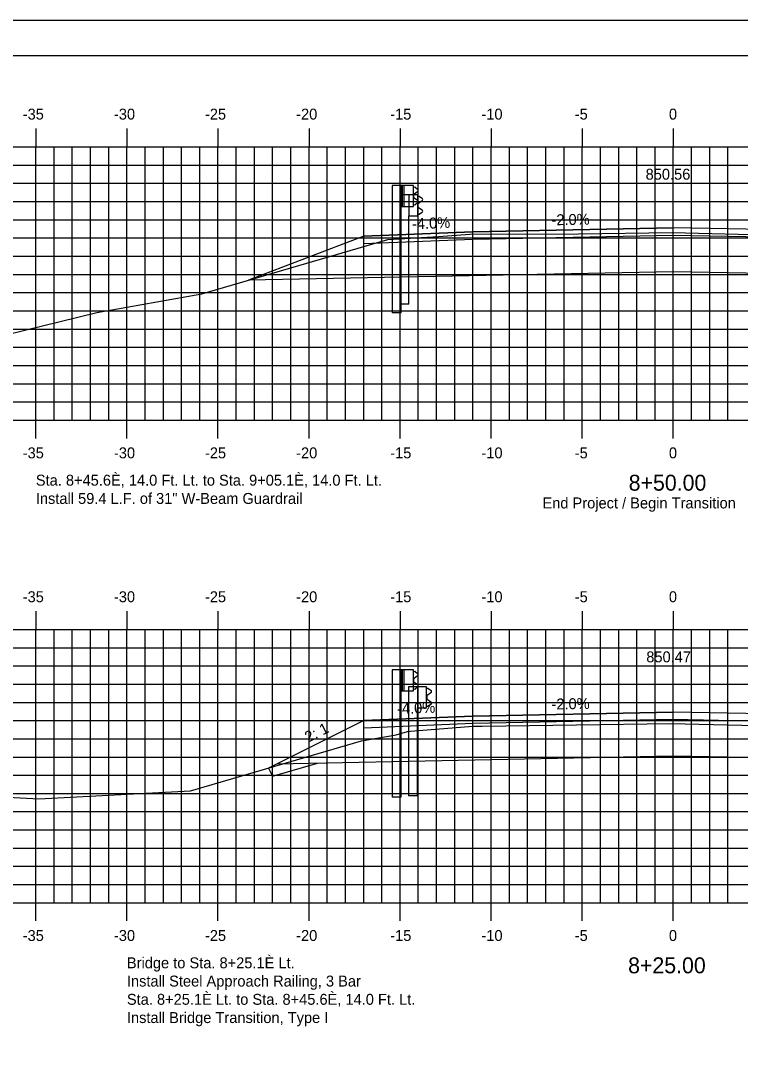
# Model space of a CAD drawing. Extents: x 2194256 to 2194747, y 863888 to 863998.
# Drawn here: x 2194440.9 to 2194480.4, y 863942.1 to 863998.4 of the extents above; entities that cross this region are included whole.
import ezdxf

# ---------------------------------------------------------------- set-up
doc = ezdxf.new("R2010")
doc.units = 0
for name, color, linetype in [('ANNOTATION', 7, 'Continuous'), ('BORDER', 7, 'Continuous'), ('D_Guardrail_Beam_Lt', 7, 'Continuous'), ('H_V ANNOTATION', 7, 'Continuous'), ('MAJOR', 7, 'Continuous'), ('MINOR', 7, 'Continuous'), ('PLOT BOUNDARY', 7, 'Continuous'), ('S_Guardrail_Beam', 7, 'Continuous'), ('S_Roadway_Centerline', 7, 'Continuous'), ('TEMPLATE', 7, 'Continuous')]:
    doc.layers.add(name, color=color, linetype=linetype)

msp = doc.modelspace()

# ---------------------------------------------------------------- linework, layer by layer
at = {"layer": 'BORDER'}
msp.add_lwpolyline([(2194401.743, 863891.446), (2194561.743, 863891.446), (2194561.743, 863996.446), (2194401.743, 863996.446)], close=True, dxfattribs=at)
at = {"layer": 'D_Guardrail_Beam_Lt'}
for p, q in [((2194461.314, 863989.332), (2194461.314, 863982.332)), ((2194461.784, 863989.332), (2194461.314, 863989.332)), ((2194462.472, 863989.332), (2194461.784, 863989.332)), ((2194461.784, 863989.332), (2194461.784, 863988.166)), ((2194461.847, 863989.332), (2194461.847, 863988.166)), ((2194461.951, 863989.332), (2194461.951, 863988.166)), ((2194462.472, 863988.166), (2194462.472, 863989.332)), ((2194462.472, 863989.249), (2194462.546, 863989.235)), ((2194462.705, 863988.985), (2194462.51, 863988.849)), ((2194462.562, 863989.228), (2194462.705, 863989.128)), ((2194462.476, 863988.784), (2194462.476, 863988.714)), ((2194462.51, 863988.65), (2194462.705, 863988.513)), ((2194462.705, 863988.37), (2194462.562, 863988.27)), ((2194461.784, 863988.166), (2194462.472, 863988.166)), ((2194461.805, 863982.332), (2194461.805, 863988.166)), ((2194462.546, 863988.264), (2194462.472, 863988.249)), ((2194461.805, 863982.332), (2194461.314, 863982.332)), ((2194461.314, 863962.742), (2194461.314, 863955.742)), ((2194461.784, 863962.742), (2194461.314, 863962.742)), ((2194462.472, 863962.742), (2194461.784, 863962.742)), ((2194461.784, 863962.742), (2194461.784, 863961.576)), ((2194461.847, 863962.742), (2194461.847, 863961.576)), ((2194461.951, 863962.742), (2194461.951, 863961.576)), ((2194462.472, 863961.576), (2194462.472, 863962.742)), ((2194462.472, 863962.659), (2194462.546, 863962.645)), ((2194462.562, 863962.638), (2194462.705, 863962.538)), ((2194462.476, 863962.194), (2194462.476, 863962.124)), ((2194462.705, 863962.395), (2194462.51, 863962.259)), ((2194462.51, 863962.06), (2194462.705, 863961.923)), ((2194461.784, 863961.576), (2194462.472, 863961.576)), ((2194461.805, 863955.742), (2194461.805, 863961.576)), ((2194462.546, 863961.674), (2194462.472, 863961.659)), ((2194462.705, 863961.78), (2194462.562, 863961.68)), ((2194461.805, 863955.742), (2194461.314, 863955.742))]:
    msp.add_line(p, q, dxfattribs=at)
for centre, major_axis, start_param, end_param in [((2194462.538, 863989.194), (0.0417, 0), 0.959931, 1.376053), ((2194462.655, 863989.056), (0.0877, 0), 5.323254, 7.243116), ((2194462.555, 863988.784), (-0.0789, 0), 5.323254, 6.283185), ((2194462.555, 863988.714), (-0.0789, 0), 6.283185, 7.243116), ((2194462.655, 863988.442), (0.0877, 0), 5.323254, 7.243116), ((2194462.538, 863988.304), (0.0417, 0), 4.907132, 5.323254), ((2194462.538, 863962.604), (0.0417, 0), 0.959931, 1.376053), ((2194462.655, 863962.466), (0.0877, 0), 5.323254, 7.243116), ((2194462.555, 863962.194), (-0.0789, 0), 5.323254, 6.283185), ((2194462.555, 863962.124), (-0.0789, 0), 6.283185, 7.243116), ((2194462.655, 863961.852), (0.0877, 0), 5.323254, 7.243116), ((2194462.538, 863961.714), (0.0417, 0), 4.907132, 5.323254)]:
    msp.add_ellipse(centre, major_axis=major_axis, ratio=0.995501, start_param=start_param, end_param=end_param, dxfattribs=at)
at = {"layer": 'MAJOR'}
for p, q in [((2194441.743, 863992.448), (2194441.743, 863991.446)), ((2194446.743, 863992.448), (2194446.743, 863991.446)), ((2194451.743, 863992.448), (2194451.743, 863991.446)), ((2194456.743, 863992.448), (2194456.743, 863991.446)), ((2194461.743, 863992.448), (2194461.743, 863991.446)), ((2194466.743, 863992.448), (2194466.743, 863991.446)), ((2194471.743, 863992.448), (2194471.743, 863991.446)), ((2194476.743, 863992.448), (2194476.743, 863991.446)), ((2194406.743, 863991.446), (2194546.743, 863991.446)), ((2194441.743, 863976.446), (2194441.743, 863991.446)), ((2194446.743, 863976.446), (2194446.743, 863991.446)), ((2194451.743, 863976.446), (2194451.743, 863991.446)), ((2194456.743, 863976.446), (2194456.743, 863991.446)), ((2194461.743, 863976.446), (2194461.743, 863991.446)), ((2194466.743, 863976.446), (2194466.743, 863991.446)), ((2194471.743, 863976.446), (2194471.743, 863991.446)), ((2194476.743, 863976.446), (2194476.743, 863991.446)), ((2194406.743, 863986.446), (2194546.743, 863986.446)), ((2194406.743, 863981.446), (2194546.743, 863981.446)), ((2194406.743, 863976.446), (2194546.743, 863976.446)), ((2194441.743, 863975.444), (2194441.743, 863976.446)), ((2194446.743, 863975.444), (2194446.743, 863976.446)), ((2194451.743, 863975.444), (2194451.743, 863976.446)), ((2194456.743, 863975.444), (2194456.743, 863976.446)), ((2194461.743, 863975.444), (2194461.743, 863976.446)), ((2194466.743, 863975.444), (2194466.743, 863976.446)), ((2194471.743, 863975.444), (2194471.743, 863976.446)), ((2194476.743, 863975.444), (2194476.743, 863976.446)), ((2194441.743, 863965.948), (2194441.743, 863964.946)), ((2194446.743, 863965.948), (2194446.743, 863964.946)), ((2194451.743, 863965.948), (2194451.743, 863964.946)), ((2194456.743, 863965.948), (2194456.743, 863964.946)), ((2194461.743, 863965.948), (2194461.743, 863964.946)), ((2194466.743, 863965.948), (2194466.743, 863964.946)), ((2194471.743, 863965.948), (2194471.743, 863964.946)), ((2194476.743, 863965.948), (2194476.743, 863964.946)), ((2194406.743, 863964.946), (2194546.743, 863964.946)), ((2194406.743, 863964.946), (2194546.743, 863964.946)), ((2194441.743, 863949.946), (2194441.743, 863964.946)), ((2194446.743, 863949.946), (2194446.743, 863964.946)), ((2194451.743, 863949.946), (2194451.743, 863964.946)), ((2194456.743, 863949.946), (2194456.743, 863964.946)), ((2194461.743, 863949.946), (2194461.743, 863964.946)), ((2194466.743, 863949.946), (2194466.743, 863964.946)), ((2194471.743, 863949.946), (2194471.743, 863964.946)), ((2194476.743, 863949.946), (2194476.743, 863964.946)), ((2194406.743, 863959.946), (2194546.743, 863959.946)), ((2194406.743, 863954.946), (2194546.743, 863954.946)), ((2194406.743, 863949.946), (2194546.743, 863949.946)), ((2194441.743, 863948.944), (2194441.743, 863949.946)), ((2194446.743, 863948.944), (2194446.743, 863949.946)), ((2194451.743, 863948.944), (2194451.743, 863949.946)), ((2194456.743, 863948.944), (2194456.743, 863949.946)), ((2194461.743, 863948.944), (2194461.743, 863949.946)), ((2194466.743, 863948.944), (2194466.743, 863949.946)), ((2194471.743, 863948.944), (2194471.743, 863949.946)), ((2194476.743, 863948.944), (2194476.743, 863949.946))]:
    msp.add_line(p, q, dxfattribs=at)
at = {"layer": 'MINOR'}
for p, q in [((2194442.743, 863976.446), (2194442.743, 863991.446)), ((2194443.743, 863976.446), (2194443.743, 863991.446)), ((2194444.743, 863976.446), (2194444.743, 863991.446)), ((2194445.743, 863976.446), (2194445.743, 863991.446)), ((2194447.743, 863976.446), (2194447.743, 863991.446)), ((2194448.743, 863976.446), (2194448.743, 863991.446)), ((2194449.743, 863976.446), (2194449.743, 863991.446)), ((2194450.743, 863976.446), (2194450.743, 863991.446)), ((2194452.743, 863976.446), (2194452.743, 863991.446)), ((2194453.743, 863976.446), (2194453.743, 863991.446)), ((2194454.743, 863976.446), (2194454.743, 863991.446)), ((2194455.743, 863976.446), (2194455.743, 863991.446)), ((2194457.743, 863976.446), (2194457.743, 863991.446)), ((2194458.743, 863976.446), (2194458.743, 863991.446)), ((2194459.743, 863976.446), (2194459.743, 863991.446)), ((2194460.743, 863976.446), (2194460.743, 863991.446)), ((2194462.743, 863976.446), (2194462.743, 863991.446)), ((2194463.743, 863976.446), (2194463.743, 863991.446)), ((2194464.743, 863976.446), (2194464.743, 863991.446)), ((2194465.743, 863976.446), (2194465.743, 863991.446)), ((2194467.743, 863976.446), (2194467.743, 863991.446)), ((2194468.743, 863976.446), (2194468.743, 863991.446)), ((2194469.743, 863976.446), (2194469.743, 863991.446)), ((2194470.743, 863976.446), (2194470.743, 863991.446)), ((2194472.743, 863976.446), (2194472.743, 863991.446)), ((2194473.743, 863976.446), (2194473.743, 863991.446)), ((2194474.743, 863976.446), (2194474.743, 863991.446)), ((2194475.743, 863976.446), (2194475.743, 863991.446)), ((2194477.743, 863976.446), (2194477.743, 863991.446)), ((2194478.743, 863976.446), (2194478.743, 863991.446)), ((2194479.743, 863976.446), (2194479.743, 863991.446)), ((2194406.743, 863990.446), (2194546.743, 863990.446)), ((2194406.743, 863989.446), (2194546.743, 863989.446)), ((2194406.743, 863988.446), (2194546.743, 863988.446)), ((2194406.743, 863987.446), (2194546.743, 863987.446)), ((2194406.743, 863985.446), (2194546.743, 863985.446)), ((2194406.743, 863984.446), (2194546.743, 863984.446)), ((2194406.743, 863983.446), (2194546.743, 863983.446)), ((2194406.743, 863982.446), (2194546.743, 863982.446)), ((2194406.743, 863980.446), (2194546.743, 863980.446)), ((2194406.743, 863979.446), (2194546.743, 863979.446)), ((2194406.743, 863978.446), (2194546.743, 863978.446)), ((2194406.743, 863977.446), (2194546.743, 863977.446)), ((2194442.743, 863949.946), (2194442.743, 863964.946)), ((2194443.743, 863949.946), (2194443.743, 863964.946)), ((2194444.743, 863949.946), (2194444.743, 863964.946)), ((2194445.743, 863949.946), (2194445.743, 863964.946)), ((2194447.743, 863949.946), (2194447.743, 863964.946)), ((2194448.743, 863949.946), (2194448.743, 863964.946)), ((2194449.743, 863949.946), (2194449.743, 863964.946)), ((2194450.743, 863949.946), (2194450.743, 863964.946)), ((2194452.743, 863949.946), (2194452.743, 863964.946)), ((2194453.743, 863949.946), (2194453.743, 863964.946)), ((2194454.743, 863949.946), (2194454.743, 863964.946)), ((2194455.743, 863949.946), (2194455.743, 863964.946)), ((2194457.743, 863949.946), (2194457.743, 863964.946)), ((2194458.743, 863949.946), (2194458.743, 863964.946)), ((2194459.743, 863949.946), (2194459.743, 863964.946)), ((2194460.743, 863949.946), (2194460.743, 863964.946)), ((2194462.743, 863949.946), (2194462.743, 863964.946)), ((2194463.743, 863949.946), (2194463.743, 863964.946)), ((2194464.743, 863949.946), (2194464.743, 863964.946)), ((2194465.743, 863949.946), (2194465.743, 863964.946)), ((2194467.743, 863949.946), (2194467.743, 863964.946)), ((2194468.743, 863949.946), (2194468.743, 863964.946)), ((2194469.743, 863949.946), (2194469.743, 863964.946)), ((2194470.743, 863949.946), (2194470.743, 863964.946)), ((2194472.743, 863949.946), (2194472.743, 863964.946)), ((2194473.743, 863949.946), (2194473.743, 863964.946)), ((2194474.743, 863949.946), (2194474.743, 863964.946)), ((2194475.743, 863949.946), (2194475.743, 863964.946)), ((2194477.743, 863949.946), (2194477.743, 863964.946)), ((2194478.743, 863949.946), (2194478.743, 863964.946)), ((2194479.743, 863949.946), (2194479.743, 863964.946)), ((2194406.743, 863963.946), (2194546.743, 863963.946)), ((2194406.743, 863962.946), (2194546.743, 863962.946)), ((2194406.743, 863961.946), (2194546.743, 863961.946)), ((2194406.743, 863960.946), (2194546.743, 863960.946)), ((2194406.743, 863958.946), (2194546.743, 863958.946)), ((2194406.743, 863957.946), (2194546.743, 863957.946)), ((2194406.743, 863956.946), (2194546.743, 863956.946)), ((2194406.743, 863955.946), (2194546.743, 863955.946)), ((2194406.743, 863953.946), (2194546.743, 863953.946)), ((2194406.743, 863952.946), (2194546.743, 863952.946)), ((2194406.743, 863951.946), (2194546.743, 863951.946)), ((2194406.743, 863950.946), (2194546.743, 863950.946))]:
    msp.add_line(p, q, dxfattribs=at)
at = {"layer": 'PLOT BOUNDARY'}
msp.add_lwpolyline([(2194393.65, 863888.387), (2194563.65, 863888.387), (2194563.65, 863998.387), (2194393.65, 863998.387)], close=True, dxfattribs=at)
at = {"layer": 'S_Guardrail_Beam'}
for p, q in [((2194461.726, 863988.82), (2194461.726, 863982.82)), ((2194462.217, 863988.82), (2194461.726, 863988.82)), ((2194462.707, 863988.82), (2194462.217, 863988.82)), ((2194462.217, 863988.82), (2194462.217, 863987.654)), ((2194462.707, 863987.654), (2194462.707, 863988.82)), ((2194462.707, 863988.747), (2194462.789, 863988.733)), ((2194462.949, 863988.483), (2194462.754, 863988.347)), ((2194462.806, 863988.726), (2194462.949, 863988.626)), ((2194462.72, 863988.282), (2194462.72, 863988.191)), ((2194462.754, 863988.127), (2194462.949, 863987.991)), ((2194462.949, 863987.848), (2194462.806, 863987.748)), ((2194462.217, 863982.82), (2194462.217, 863987.654)), ((2194462.217, 863987.654), (2194462.707, 863987.654)), ((2194462.789, 863987.741), (2194462.707, 863987.726)), ((2194462.217, 863982.82), (2194461.726, 863982.82)), ((2194462.209, 863961.807), (2194462.209, 863955.807)), ((2194462.7, 863961.807), (2194462.209, 863961.807)), ((2194463.19, 863961.807), (2194462.7, 863961.807)), ((2194462.7, 863961.807), (2194462.7, 863960.64)), ((2194463.19, 863960.64), (2194463.19, 863961.807)), ((2194463.19, 863961.734), (2194463.272, 863961.719)), ((2194463.432, 863961.47), (2194463.237, 863961.333)), ((2194463.289, 863961.713), (2194463.432, 863961.613)), ((2194463.203, 863961.269), (2194463.203, 863961.178)), ((2194463.237, 863961.114), (2194463.432, 863960.977)), ((2194463.432, 863960.834), (2194463.289, 863960.734)), ((2194462.7, 863955.807), (2194462.7, 863960.64)), ((2194462.7, 863960.64), (2194463.19, 863960.64)), ((2194463.272, 863960.727), (2194463.19, 863960.713)), ((2194462.7, 863955.807), (2194462.209, 863955.807))]:
    msp.add_line(p, q, dxfattribs=at)
for centre, major_axis, start_param, end_param in [((2194462.799, 863988.282), (-0.0789, 0), 5.323254, 6.283185), ((2194462.782, 863988.692), (0.0417, 0), 0.959931, 1.396263), ((2194462.899, 863988.555), (0.0877, 0), 5.323254, 7.243116), ((2194462.799, 863988.191), (-0.0789, 0), 6.283185, 7.243116), ((2194462.899, 863987.919), (0.0877, 0), 5.323254, 7.243116), ((2194462.782, 863987.782), (0.0417, 0), 4.886922, 5.323254), ((2194463.282, 863961.269), (-0.0789, 0), 5.323254, 6.283185), ((2194463.265, 863961.679), (0.0417, 0), 0.959931, 1.396263), ((2194463.382, 863961.541), (0.0877, 0), 5.323254, 7.243116), ((2194463.282, 863961.178), (-0.0789, 0), 6.283185, 7.243116), ((2194463.382, 863960.906), (0.0877, 0), 5.323254, 7.243116), ((2194463.265, 863960.768), (0.0417, 0), 4.886922, 5.323254)]:
    msp.add_ellipse(centre, major_axis=major_axis, ratio=0.995501, start_param=start_param, end_param=end_param, dxfattribs=at)
at = {"layer": 'S_Roadway_Centerline'}
for points in [[(2194406.743, 863984.776), (2194413.814, 863984.462), (2194422.331, 863983.975), (2194424.939, 863983.173), (2194440.092, 863981.136), (2194445.1, 863982.351), (2194450.863, 863983.373), (2194461.063, 863986.367), (2194463.856, 863986.522), (2194465.566, 863986.66), (2194471.54, 863986.672), (2194476.678, 863986.745), (2194482.483, 863986.609), (2194488.569, 863986.453), (2194490.962, 863986.285), (2194492.004, 863986.208), (2194497.241, 863986.134), (2194498.885, 863986.051), (2194505.695, 863985.992)], [(2194436.828, 863955.919), (2194441.916, 863955.643), (2194450.241, 863956.094), (2194459.622, 863958.832), (2194461.531, 863959.171), (2194462.152, 863959.353), (2194462.322, 863959.362), (2194465.731, 863959.637), (2194466.254, 863959.638), (2194476.612, 863959.784), (2194488.315, 863959.51), (2194488.716, 863959.5), (2194489.419, 863959.45), (2194492.028, 863959.243), (2194494.216, 863959.118), (2194496.931, 863958.932), (2194497.146, 863958.884), (2194498.014, 863958.878), (2194503.173, 863959.04), (2194509.394, 863958.986)]]:
    msp.add_lwpolyline(points, dxfattribs=at)
at = {"layer": 'TEMPLATE'}
for p, q in [((2194465.743, 863986.786), (2194459.743, 863986.546)), ((2194465.743, 863986.786), (2194476.743, 863987.006)), ((2194476.743, 863987.006), (2194465.743, 863986.786)), ((2194487.743, 863986.786), (2194476.743, 863987.006)), ((2194459.743, 863986.546), (2194453.417, 863984.123)), ((2194476.743, 863986.589), (2194465.743, 863986.369)), ((2194487.743, 863986.369), (2194476.743, 863986.589)), ((2194476.743, 863984.589), (2194453.417, 863984.123)), ((2194498.527, 863984.153), (2194476.743, 863984.589)), ((2194465.743, 863960.196), (2194459.743, 863959.956)), ((2194465.743, 863960.196), (2194476.743, 863960.416)), ((2194476.743, 863960.416), (2194465.743, 863960.196)), ((2194487.743, 863960.196), (2194476.743, 863960.416)), ((2194459.743, 863959.956), (2194454.513, 863957.341)), ((2194476.743, 863959.999), (2194465.743, 863959.779)), ((2194487.743, 863959.779), (2194476.743, 863959.999)), ((2194476.743, 863957.999), (2194454.958, 863957.563)), ((2194498.527, 863957.563), (2194476.743, 863957.999)), ((2194454.513, 863957.341), (2194454.736, 863956.894))]:
    msp.add_line(p, q, dxfattribs=at)
for points in [[(2194459.743, 863986.546), (2194459.743, 863986.546), (2194465.743, 863986.786)], [(2194465.743, 863986.369), (2194459.743, 863986.129), (2194459.743, 863986.546)], [(2194459.743, 863959.956), (2194459.743, 863959.956), (2194465.743, 863960.196)], [(2194465.743, 863959.779), (2194459.743, 863959.539), (2194459.743, 863959.956)], [(2194454.74, 863956.886), (2194457.214, 863957.609)]]:
    msp.add_lwpolyline(points, dxfattribs=at)

# ---------------------------------------------------------------- texts
at = {"layer": 'ANNOTATION'}
for s, p in [('850.56', (2194475.223, 863989.646)), ('Sta. 8+45.6È, 14.0 Ft. Lt. to Sta. 9+05.1È, 14.0 Ft. Lt.', (2194441.743, 863972.846)), ('Install 59.4 L.F. of 31" W-Beam Guardrail', (2194441.743, 863971.844)), ('End Project / Begin Transition', (2194469.559, 863971.596)), ('850.47', (2194475.26, 863963.146)), ('Bridge to Sta. 8+25.1È Lt.', (2194446.743, 863946.346)), ('Install Steel Approach Railing, 3 Bar', (2194446.743, 863945.344)), ('Sta. 8+25.1È Lt. to Sta. 8+45.6È, 14.0 Ft. Lt.', (2194446.743, 863944.342)), ('Install Bridge Transition, Type I', (2194446.743, 863943.34))]:
    msp.add_text(s, height=0.6, dxfattribs=at).set_placement(p)
for s, rotation, p in [('-2.0%', 1.1458, (2194470.06, 863987.139)), ('-4.0%', 2.2906, (2194462.406, 863986.919)), ('-4.0%', 2.2906, (2194461.588, 863960.297)), ('-2.0%', 1.1458, (2194470.06, 863960.549)), ('2: 1', 26.5651, (2194456.692, 863958.729))]:
    msp.add_text(s, height=0.6, rotation=rotation, dxfattribs=at).set_placement(p)
at = {"layer": 'H_V ANNOTATION'}
for s, height, p in [('-35', 0.6, (2194441.023, 863992.946)), ('-30', 0.6, (2194446.031, 863992.946)), ('-25', 0.6, (2194451.028, 863992.946)), ('-20', 0.6, (2194456.036, 863992.946)), ('-15', 0.6, (2194461.2, 863992.946)), ('-10', 0.6, (2194466.208, 863992.946)), ('-5', 0.6, (2194471.333, 863992.946)), ('0', 0.6, (2194476.502, 863992.946)), ('-35', 0.6, (2194441.023, 863974.346)), ('-30', 0.6, (2194446.031, 863974.346)), ('-25', 0.6, (2194451.028, 863974.346)), ('-20', 0.6, (2194456.036, 863974.346)), ('-15', 0.6, (2194461.2, 863974.346)), ('-10', 0.6, (2194466.208, 863974.346)), ('-5', 0.6, (2194471.333, 863974.346)), ('0', 0.6, (2194476.502, 863974.346)), ('8+50.00', 0.875, (2194474.293, 863972.571)), ('-35', 0.6, (2194441.023, 863966.446)), ('-30', 0.6, (2194446.031, 863966.446)), ('-25', 0.6, (2194451.028, 863966.446)), ('-20', 0.6, (2194456.036, 863966.446)), ('-15', 0.6, (2194461.2, 863966.446)), ('-10', 0.6, (2194466.208, 863966.446)), ('-5', 0.6, (2194471.333, 863966.446)), ('0', 0.6, (2194476.502, 863966.446)), ('-35', 0.6, (2194441.023, 863947.846)), ('-30', 0.6, (2194446.031, 863947.846)), ('-25', 0.6, (2194451.028, 863947.846)), ('-20', 0.6, (2194456.036, 863947.846)), ('-15', 0.6, (2194461.2, 863947.846)), ('-10', 0.6, (2194466.208, 863947.846)), ('-5', 0.6, (2194471.333, 863947.846)), ('0', 0.6, (2194476.502, 863947.846)), ('8+25.00', 0.875, (2194474.261, 863946.071))]:
    msp.add_text(s, height=height, dxfattribs=at).set_placement(p)

doc.saveas('drawing.dxf')
